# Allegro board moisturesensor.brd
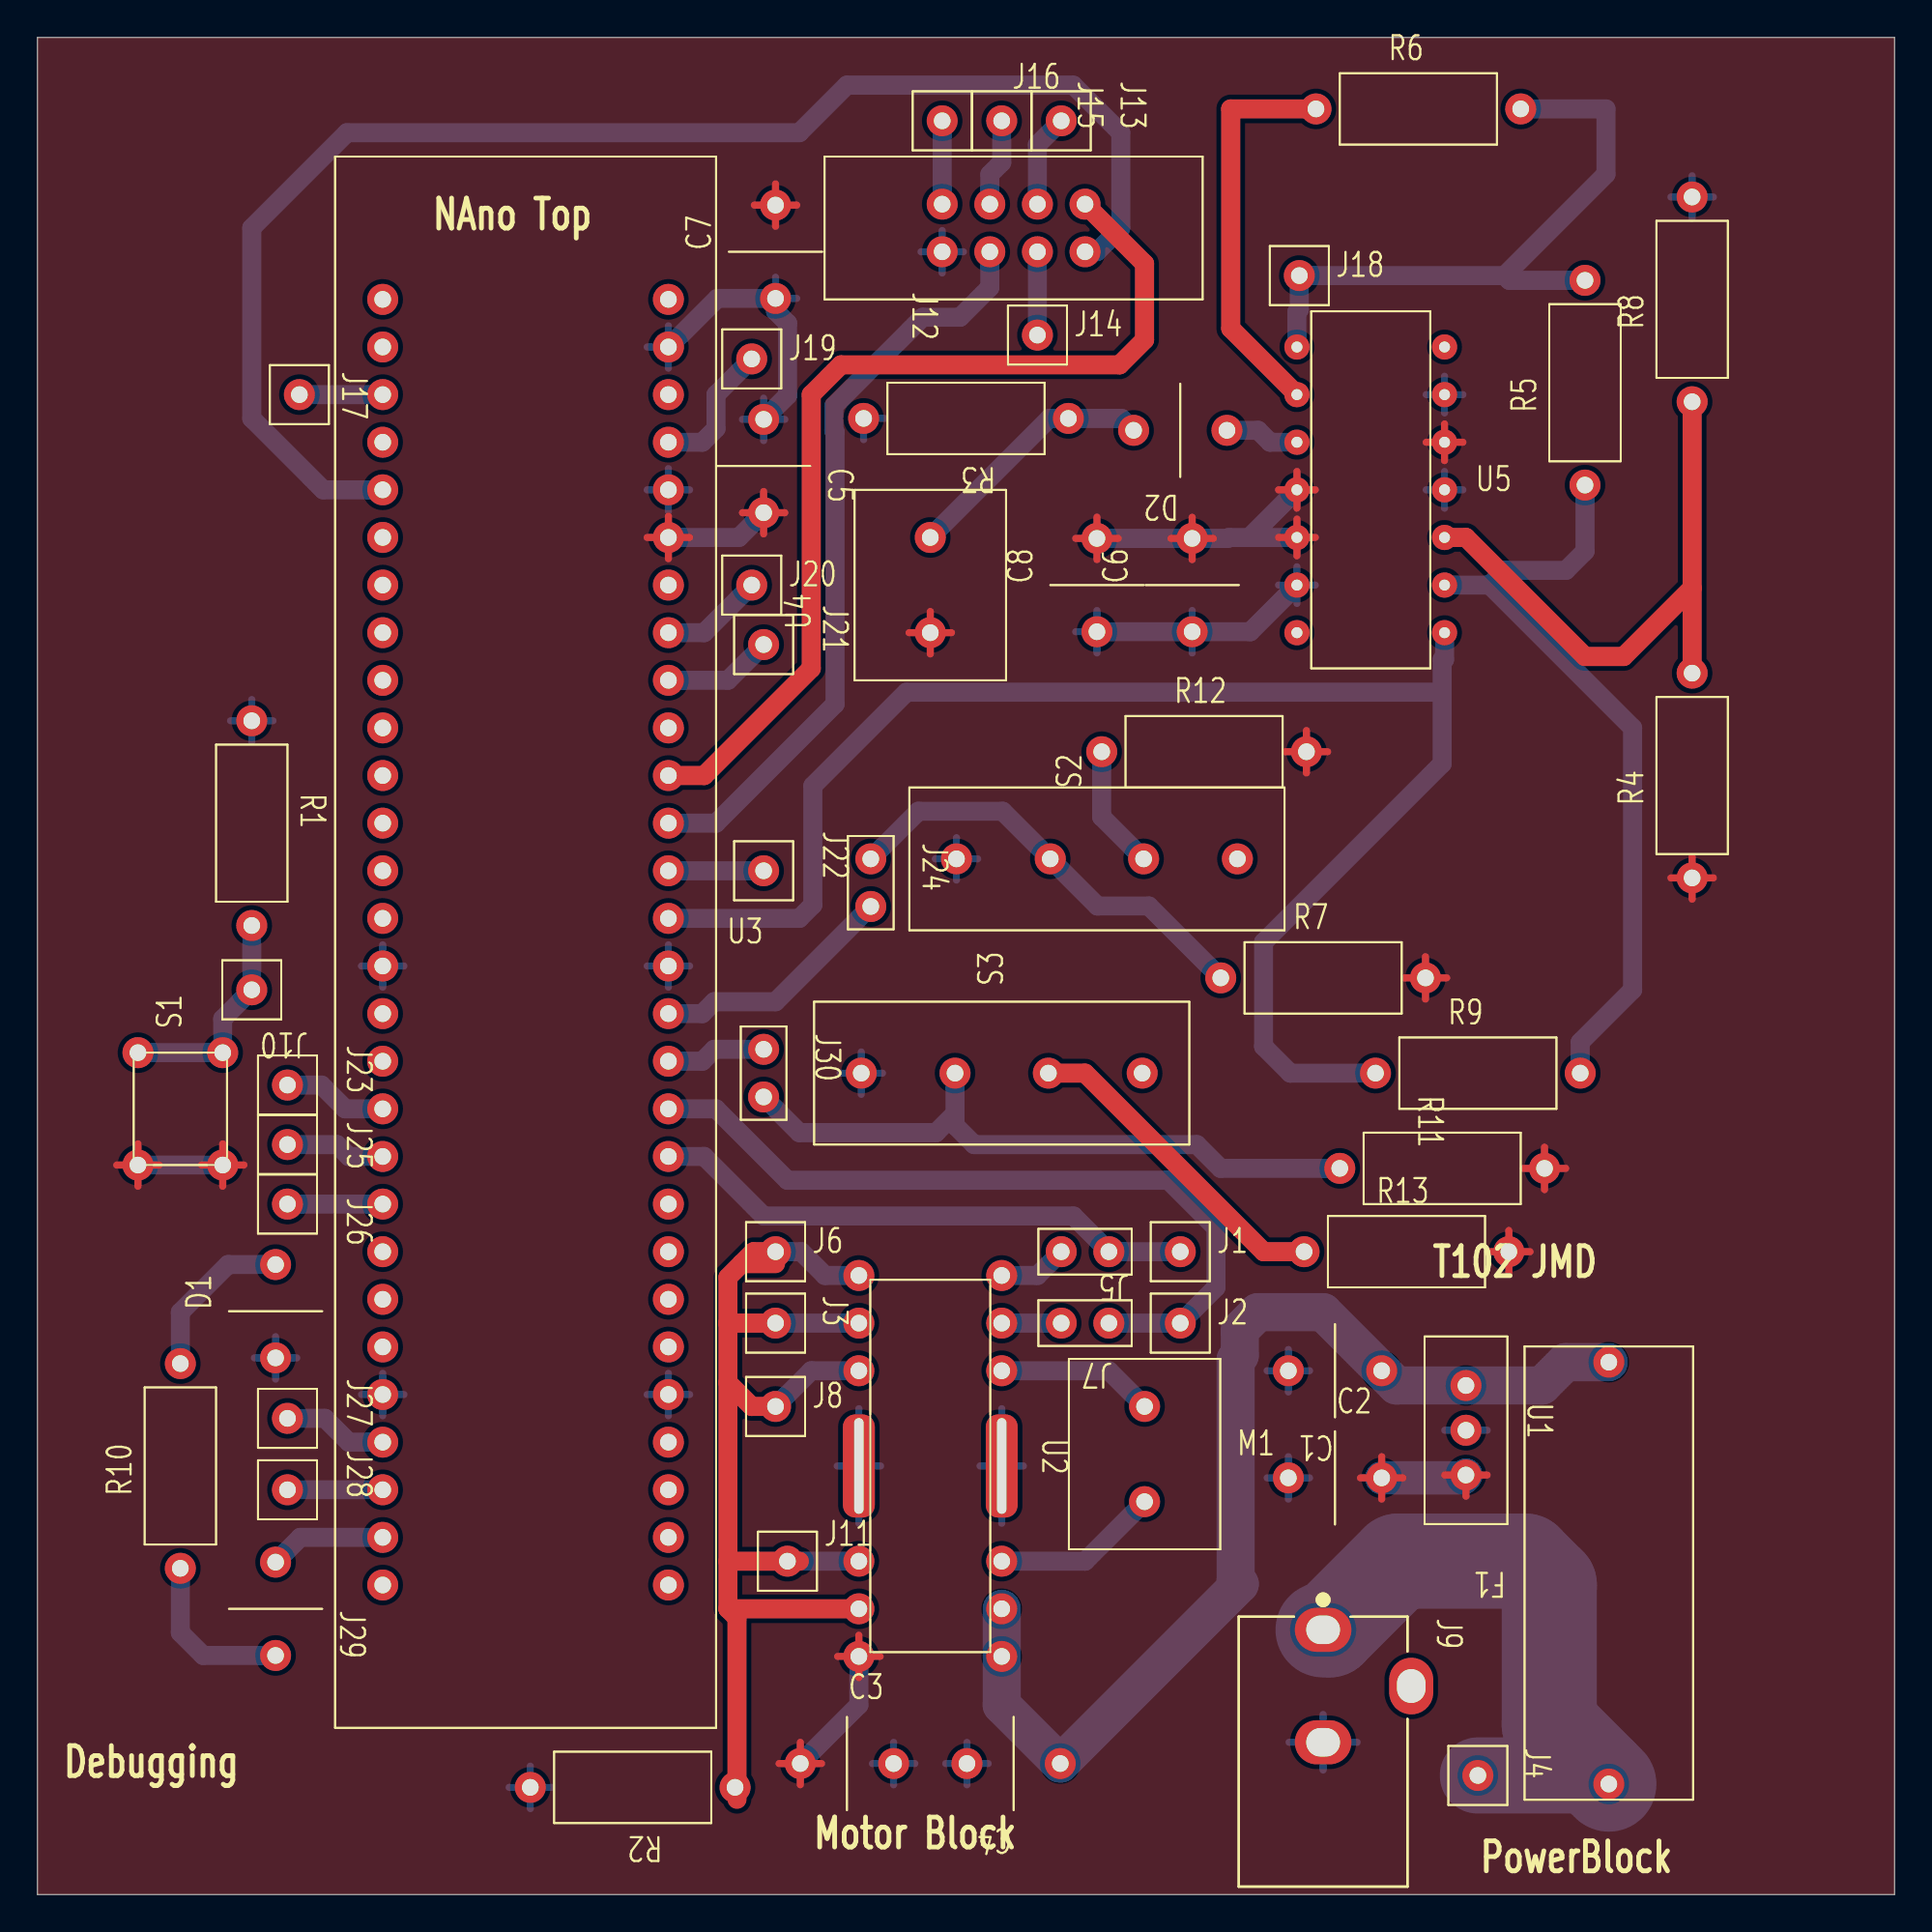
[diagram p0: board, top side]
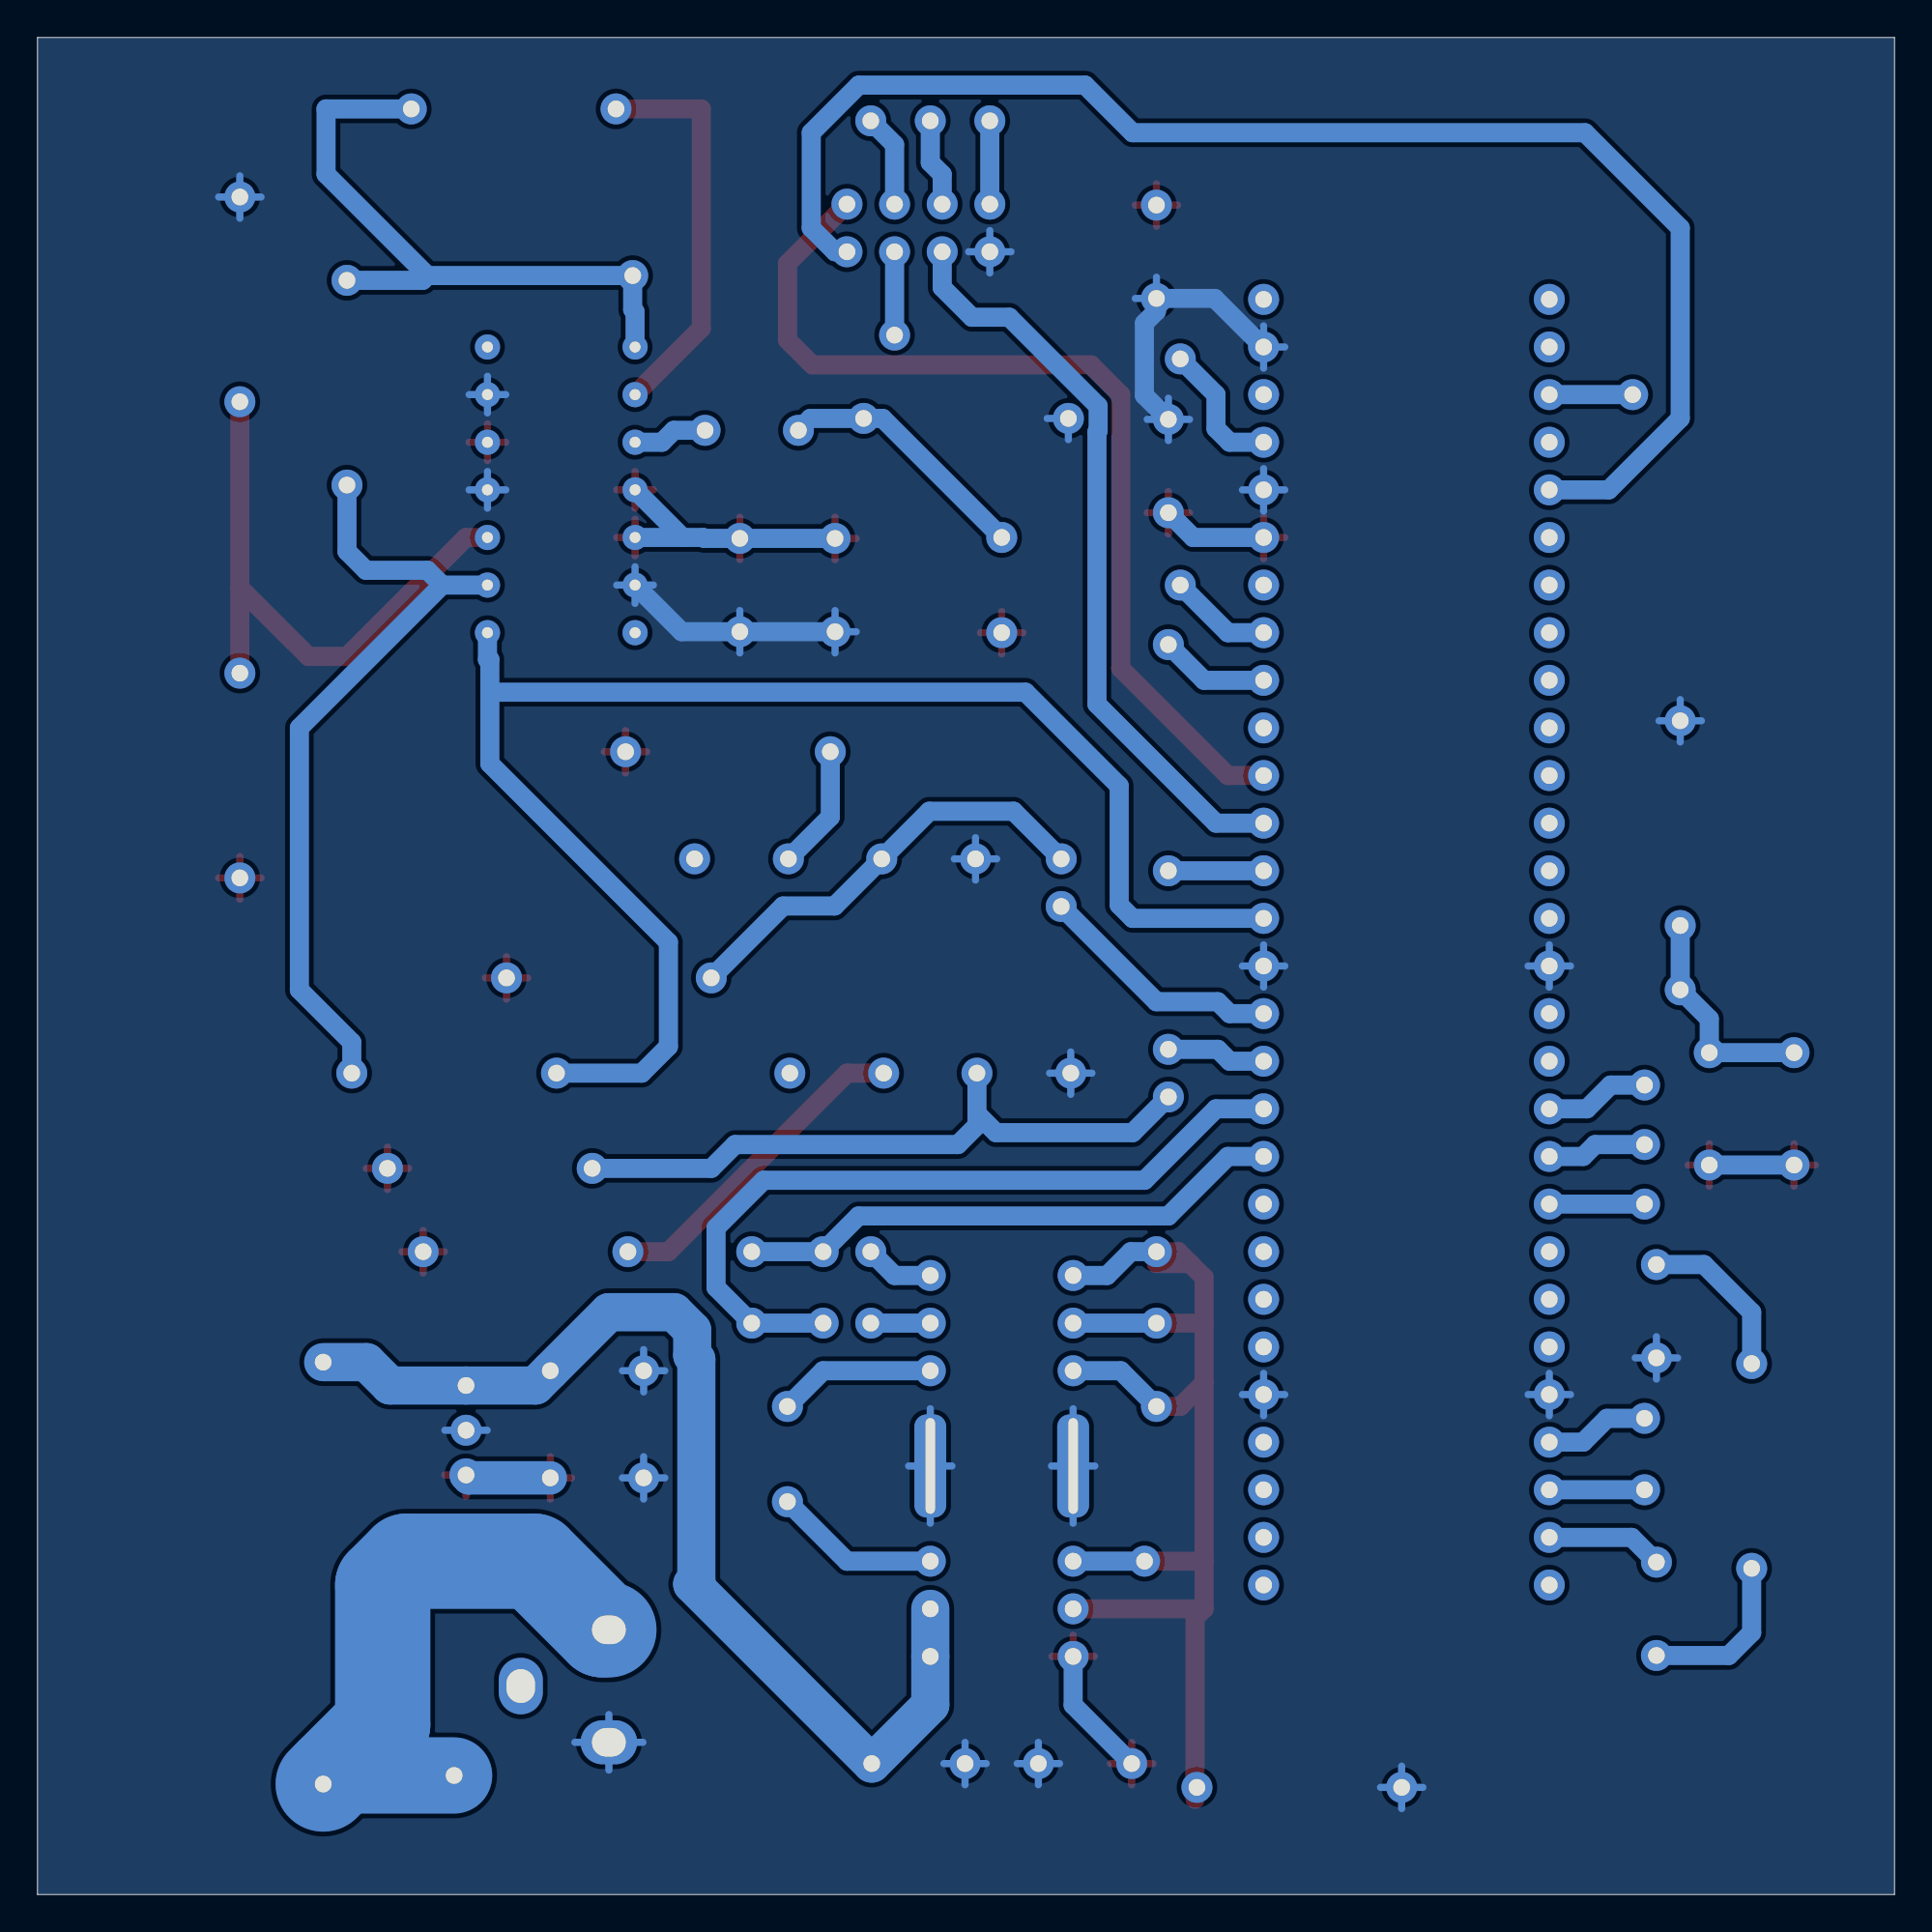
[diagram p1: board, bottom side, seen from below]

Outline 99.06 x 99.06 mm; copper layers: TOP, BOTTOM. Coordinates in mm from the lower left corner of the outline.
Outline path: 0,99.06 0,0 99.06,0 99.06,99.06 0,99.06

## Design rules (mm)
constraint set DEFAULT: min track width 0.381

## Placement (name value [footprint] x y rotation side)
C1  .33uf 50V  [CAPACITOR]  69.22 27.94 180 top
C2  .1uF 50V  [CAPACITOR]  69.22 22.22 0 top
C3  .1uF 50V  [CAPACITOR]  43.18 6.99 0 top
C4  .1uF 50V  [CAPACITOR]  52.07 6.99 180 top
C5  .1uF 50V  [CAPACITOR]  38.73 76.2 270 top
C6  .1uF 50V  [CAPACITOR]  61.59 69.85 90 top
C7  .1uF 50V  [CAPACITOR]  39.37 87.63 90 top
C8  .1uF 50V  [CAPACITOR]  56.52 69.85 90 top
D1  BlueLED  [CAPACITOR]  12.7 31.12 90 top
D2  DIODE  [CAPACITOR]  60.96 78.11 180 top
F1  FUSE 1A  [FUSEHOLDER]  83.82 17.15 180 top
J1  TP2  [MALEPINHOLE]  60.96 34.29 0 top
J2  TP3  [MALEPINHOLE]  60.96 30.48 0 top
J3  TP5  [MALEPINHOLE]  39.37 30.48 0 top
J4  TP12  [MALEPINHOLE]  76.83 6.35 0 top
J5  Jumper_JMD  [JUMPER]  55.88 34.29 270 top
J6  TP4  [MALEPINHOLE]  39.37 34.29 0 top
J7  Jumper_JMD  [JUMPER]  55.88 30.48 270 top
J8  TP6  [MALEPINHOLE]  39.37 26.03 0 top
J9  Barrel_Jack_Switch_JMD  [BARRELJACKDEVELOPERS_JMD]  68.58 7.62 270 top
J10  TP13  [MALEPINHOLE]  11.43 48.26 270 top
J11  TP7  [MALEPINHOLE]  40 17.78 0 top
J12  RibbonCable  [DIP8PIN]  52.07 88.9 270 top
J13  TP8  [MALEPINHOLE]  54.61 94.62 0 top
J14  TP9  [MALEPINHOLE]  53.34 83.19 0 top
J15  TP10  [MALEPINHOLE]  51.44 94.62 0 top
J16  TP11  [MALEPINHOLE]  48.26 94.62 0 top
J17  gpio_RF0  [MALEPINHOLE]  13.97 80.01 0 top
J18  TP1  [MALEPINHOLE]  67.31 86.36 0 top
J19  gpio_RB7  [MALEPINHOLE]  38.1 81.92 0 top
J20  gpio_RA6  [MALEPINHOLE]  38.1 69.85 0 top
J21  gpio_RB3  [MALEPINHOLE]  38.73 66.68 0 top
J22  gpio_RA1  [MALEPINHOLE]  38.73 54.61 0 top
J23  gpio_RE2  [MALEPINHOLE]  13.34 43.18 0 top
J24  Jumper_JMD  [JUMPER]  44.45 53.97 0 top
J25  gpio_RC7  [MALEPINHOLE]  13.34 40 0 top
J26  gpio_RD0  [MALEPINHOLE]  13.34 36.83 0 top
J27  gpio_RF0  [MALEPINHOLE]  13.34 25.4 0 top
J28  gpio_RF1  [MALEPINHOLE]  13.34 21.59 0 top
J29  Jumper_JMD  [CAPACITOR]  12.7 15.24 270 top
J30  Jumper_JMD  [JUMPER]  38.73 43.81 0 top
M1  Motor_DC_JMD  [SCREWTERMINAL]  59.06 23.5 0 top
R1  1k .25w  [RESISTOR_INTRO]  11.43 57.15 270 top
R2  1k .25w  [RESISTOR_INTRO]  31.75 5.72 180 top
R3  10k .25W  [RESISTOR_INTRO]  49.53 78.74 180 top
R4  10k .25W  [RESISTOR_INTRO]  88.27 59.69 90 top
R5  1k .25w  [RESISTOR_INTRO]  82.55 80.64 90 top
R6  1k .25w  [RESISTOR_INTRO]  73.66 95.25 0 top
R7  100k .25W  [RESISTOR_INTRO]  68.58 48.9 0 top
R8  10k .25W  [RESISTOR_INTRO]  88.27 85.09 90 top
R9  10k .25W  [RESISTOR_INTRO]  76.83 43.81 0 top
R10  220 .25W  [RESISTOR_INTRO]  7.62 22.86 90 top
R11  10k .25W  [RESISTOR_INTRO]  74.93 38.74 0 top
R12  10k .25W  [RESISTOR_INTRO]  62.23 60.96 0 top
R13  2k .25W  [RESISTOR_INTRO]  73.03 34.29 0 top
S1  SW_DPST_JMD  [SW_DPST]  7.62 41.91 90 top
S2  Switch_limit_JMD  [LIMITSWITCH]  56.52 55.25 90 top
S3  Switch_limit_JMD  [LIMITSWITCH]  51.44 43.81 90 top
U1  LM7805_JMD  [LINEARVOLTREG]  76.2 24.77 0 top
U2  FAN8011N_JMD  [HBRIDGEWITHFIN]  45.09 22.86 0 top
U3  PIC18F57Q43_JMD  [MICROCHIP_PIC18F57Q43]  26.03 50.8 0 top
U4  MS_JMD  [SCREWTERMINAL]  47.62 69.85 180 top
U5  MCP6004_JMD  [OPAMPJMD]  71.12 74.93 0 top

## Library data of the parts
C1-C8 = CAPACITOR NON-POL
D1 = LED
D2 = DIODE
F1 = FUSE
J1-J4 J6 J10 J13-J17 J20-J23 J25-J28 = MalePinPlaceHolder_JMD
J5 J7 J24 J29 J30 = jumper_jmd
J8 = malePinPlaceHolderOutput_JMD_0
J9 = Barrel_Jack_Switch_JMD
J11 = malePinPlaceHolderOutput_JMD_1
J12 = CONN TRBLK 8
J18 = MalePinPlaceHolder_JMD_6
J19 = malePinPlaceHolderOutput_JMD
M1 = Motor_DC_JMD
R1-R13 = RESISTOR
S1 = SW_DPST_JMD
S2 S3 = 463093691402_Limit_JMD
U1 = LM7805_JMD_0
U2 = FAN8011N_JMD_2
U3 = PIC18F57Q43_JMD
U4 = MoistureSenosr_JMD
U5 = MCP6004_JMD

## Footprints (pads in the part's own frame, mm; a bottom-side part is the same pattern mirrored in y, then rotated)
BARRELJACKDEVELOPERS_JMD
  oval 2.35x3.016 hole 1.52x1.8 unplated: (-6.5,0) (-0.5,0)
  oval 3.016x2.35 hole 1.8x1.52 unplated: (-3.5,4.7)
CAPACITOR
  round 1.651 hole 0.889: 1(-2.489,0) 2(2.489,0)
DIP8PIN
  round 1.651 hole 0.889: 1(-1.27,3.81) 2(1.27,3.81) 3(-1.27,1.27) 4(1.27,1.27) 5(-1.27,-1.27) 6(1.27,-1.27) 7(-1.27,-3.81) 8(1.27,-3.81)
FUSEHOLDER
  round 1.651 hole 0.889: 1(0,11.252) 2(0,-11.252)
HBRIDGEWITHFIN
  round 1.651 hole 0.889: 1(-1.27,10.16) 2(-1.27,7.62) 3(-1.27,5.08) 4(-1.27,-5.08) 5(-1.27,-7.62) 6(-1.27,-10.16) 7(6.35,-10.16) 8(6.35,-7.62) 9(6.35,-5.08) 10(6.35,5.08) 11(6.35,7.62) 12(6.35,10.16)
  rrect 1.7x5.5 hole 0.5x5.105: FIN(-1.27,0) FIN2(6.35,0)
JUMPER
  round 1.651 hole 0.889: 1(0,1.27) 2(0,-1.27)
LIMITSWITCH
  round 1.651 hole 0.889: 1(0,7.493) 2(0,2.489) 3(0,-2.489) 4(0,-7.493)
LINEARVOLTREG
  round 1.651 hole 0.889: 1(0,2.388) 2(0,0) 3(0,-2.388)
MALEPINHOLE
  round 1.651 hole 0.889: 1(0,0)
MICROCHIP_PIC18F57Q43
  round 1.651 hole 0.889: 1(7.62,34.29) 2(7.62,31.75) 3(7.62,29.21) 4(7.62,26.67) 5(7.62,24.13) 6(7.62,21.59) 7(7.62,19.05) 8(7.62,16.51) 9(7.62,13.97) 10(7.62,11.43) 11(7.62,8.89) 12(7.62,6.35) 13(7.62,3.81) 14(7.62,1.27) 15(7.62,-1.27) 16(7.62,-3.81) 17(7.62,-6.35) 18(7.62,-8.89) 19(7.62,-11.43) 20(7.62,-13.97) 21(7.62,-16.51) 22(7.62,-19.05) 23(7.62,-21.59) 24(7.62,-24.13) 25(7.62,-26.67) 26(7.62,-29.21) 27(7.62,-31.75) 28(7.62,-34.29) 29(-7.62,34.29) 30(-7.62,31.75) 31(-7.62,29.21) 32(-7.62,26.67) 33(-7.62,24.13) 34(-7.62,21.59) 35(-7.62,19.05) 36(-7.62,16.51) 37(-7.62,13.97) 38(-7.62,11.43) 39(-7.62,8.89) 40(-7.62,6.35) 41(-7.62,3.81) 42(-7.62,1.27) 43(-7.62,-1.27) 44(-7.62,-3.81) 45(-7.62,-6.35) 46(-7.62,-8.89) 47(-7.62,-11.43) 48(-7.62,-13.97) 49(-7.62,-16.51) 50(-7.62,-19.05) 51(-7.62,-21.59) 52(-7.62,-24.13) 53(-7.62,-26.67) 54(-7.62,-29.21) 55(-7.62,-31.75) 56(-7.62,-34.29)
OPAMPJMD
  round 1.346 hole 0.584: 1(-3.937,7.62) 2(-3.937,5.08) 3(-3.937,2.54) 4(-3.937,0) 5(-3.937,-2.54) 6(-3.937,-5.08) 7(-3.937,-7.62) 8(3.937,-7.62) 9(3.937,-5.08) 10(3.937,-2.54) 11(3.937,0) 12(3.937,2.54) 13(3.937,5.08) 14(3.937,7.62)
RESISTOR_INTRO
  round 1.651 hole 0.889: 1(-5.461,0) 2(5.461,0)
SCREWTERMINAL
  round 1.651 hole 0.889: 1(0,2.54) 2(0,-2.54)
SW_DPST
  round 1.651 hole 0.889: 1(-2.997,2.261) 2(2.997,2.261) 3(-2.997,-2.261) 4(2.997,-2.261)

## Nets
+5V: C2.2 C3.1 C5.2 C6.2 C7.2 C8.2 R4.1 R7.2 R11.2 R12.2 R13.2 S1.1(\PASSIVE\) S1.3 U1.3(\OUTPUT\) U2.6(\VCC\) U3.6(\VTG\) U4.1 U5.4 U5.5 U5.12
+9V: C1.1 C4.1 F1.2 U1.1 U2.7 U2.8
GND: C1.2 C2.1 C3.2 C4.2 C5.1 C6.1 C7.1 C8.1 D1.1(\CATHODE\) J12.8 R1.1 R2.2 R3.2 R8.2 S2.1 S3.1 U1.2 U2.FIN U2.FIN2 U3.2 U3.5 U3.15 U3.24 U3.43 U3.52 U5.6 U5.11(\VSS\) U5.13
VBUS: U3.1
AMPSIG: R5.1 R9.2 U5.9
BACKLIMIT: J30.1 U3.17
INVAMP: R6.1 U5.2
MRETURN: J12.6 U3.12
MSOUT: R9.1 U3.14 U5.8
OUT1: J18.1(\PORT\) R5.2 R6.2 U5.1
PSIGNAL: J12.1 U3.11
RSIGNAL: J12.2 U3.33
SIGBACK: J1.1(\PORT\) J5.1 U3.19
SIGFORWARD: J2.1(\PORT\) J7.1 U3.18
VREF: R4.2 R8.1 U5.10
N91840: J3.1(\PORT\) J6.1(\PORT\) J8.1 J11.1 R2.1 U2.1 U2.2 U2.3 U2.4 U2.5
N91848: J7.2 U2.11
N91894: M1.1 U2.10
N91902: F1.1 J4.1(\PORT\)
N92202: M1.2(-) U2.9
N93412: J24.2 U3.16
N93642: J27.1(\PORT\) U3.53
N93710: J29.1 U3.55
N93718: J29.2 R10.1
N93780: J30.2 R11.1 S3.2
N93800: R13.1 S3.3
N113659: J10.1(\PORT\) R1.2 S1.2 S1.4
N116351: J24.1 R7.1 S2.2
N125765: D2.2 R3.1 U4.2
N125778: D2.1(\K\) U5.3
N129031: J12.4 J14.1(\PORT\)
N923142: J12.3 J13.1(\PORT\)
N923144: J12.5 J15.1(\PORT\)
N923146: J12.7 J16.1(\PORT\)
N926043: J19.1 U3.4
N926047: J20.1(\PORT\) U3.8
N926048: J21.1(\PORT\) U3.9
N932342: R12.1 S2.3
N934900: D1.2 R10.2
N9170211: J5.2 U2.12
N9260427: J17.1(\PORT\) U3.31
N9260442: J23.1(\PORT\) U3.46
N9260443: J25.1(\PORT\) U3.47
N9260444: J26.1(\PORT\) U3.48
N9260450: J28.1(\PORT\) U3.54
N9260454: J22.1(\PORT\) U3.13

Pads without a net: S2 4; S3 4; U3 3 7 10 20 21 22 23 25 26 27 28 29 30 32 34 35 36 37 38 39 40 41 42 44 45 49 50 51 56; U5 7 14

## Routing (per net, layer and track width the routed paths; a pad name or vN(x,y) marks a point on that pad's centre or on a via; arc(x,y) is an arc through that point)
+5V: length 123.5
  TOP w0.381: 46.49,67.31 U4.1 ; U4.1 47.62,68.44 ; U4.1 47.62,66.18 ; U4.1 48.76,67.31 ; 87.13,54.23 R4.1 ; R4.1 88.27,53.1 ; R4.1 88.27,55.36 ; R4.1 89.4,54.23 ; 55.38,72.34 C8.2 ; C8.2 56.52,71.21 ; C8.2 57.65,72.34 ; C8.2 56.52,73.47 ; 37.6,73.71 C5.2 ; C5.2 39.87,73.71 ; C5.2 38.73,74.84 ; C5.2 38.73,72.58 ; 71.7,21.09 C2.2 ; C2.2 72.84,22.22 ; C2.2 71.7,23.36 ; C2.2 70.57,22.22 ; 5.36,37.78 S1.1 ; S1.1 6.49,38.91 ; S1.1 5.36,40.04 ; S1.1 4.23,38.91 ; R7.2 74.04,50.03 ; R7.2 72.91,48.9 ; R7.2 74.04,47.76 ; R7.2 75.17,48.9 ; C7.2 40.5,90.12 ; C7.2 39.37,88.99 ; C7.2 39.37,91.25 ; C7.2 38.24,90.12 ; R13.2 78.49,35.42 ; R13.2 77.36,34.29 ; R13.2 78.49,33.16 ; R13.2 79.62,34.29 ; R11.2 81.52,38.74 ; R11.2 79.26,38.74 ; R11.2 80.39,37.6 ; R11.2 80.39,39.87 ; U5.12 75.06,78.45 ; U5.12 75.06,76.49 ; U5.12 76.04,77.47 ; U5.12 74.08,77.47 ; U5.5 68.16,72.39 ; U5.5 67.18,71.41 ; U5.5 67.18,73.37 ; U5.5 66.2,72.39 ; 42.68,12.7 U2.6 ; U2.6 44.95,12.7 ; U2.6 43.81,13.83 ; U2.6 43.81,11.57 ; S1.3 9.88,40.04 ; S1.3 11.01,38.91 ; S1.3 9.88,37.78 ; S1.3 8.75,38.91 ; 76.2,21.25 U1.3 ; U1.3 75.07,22.38 ; U1.3 77.33,22.38 ; C6.2 62.73,72.34 ; C6.2 61.59,73.47 ; C6.2 61.59,71.21 ; C6.2 60.46,72.34 ; U5.4 67.18,75.91 ; U5.4 68.16,74.93 ; U5.4 66.2,74.93 ; U5.4 67.18,73.95 ; U3.6 33.66,73.52 ; U3.6 32.52,72.39 ; U3.6 33.66,71.26 ; U3.6 34.79,72.39 ; C3.1 41.82,6.99 ; C3.1 40.69,5.85 ; C3.1 40.69,8.12 ; C3.1 39.56,6.99 ; 67.69,59.83 R12.2 ; R12.2 67.69,62.09 ; R12.2 66.56,60.96 ; R12.2 68.82,60.96
  BOTTOM w1.016: U3.6 37.41,72.39 C5.2 ; 64.64,72.39 63.55,72.39 63.5,72.34 C6.2 C8.2 ; 64.64,72.39 U5.5 ; 64.64,72.39 U5.4 ; C3.1 43.81,10.11 U2.6 ; S1.1 S1.3
  BOTTOM w1.778: C2.2 76.05,22.22 U1.3
+9V: length 59
  BOTTOM w2.032: U2.8 U2.7 51.44,10.11 C4.1 64.14,16.56 63.91,16.78 63.91,28.55 64.14,28.77 64.14,30.1 65.1,31.06 68.58,31.06 C1.1 72.49,27.15 U1.1 80.26,27.15 81.5,28.4 F1.2
GND: length 153.6
  BOTTOM w0.381: U3.24 33.66,27.8 ; U3.24 33.66,25.54 ; U3.24 32.52,26.67 ; U3.24 34.79,26.67 ; 74.08,80.01 U5.13 ; U5.13 76.04,80.01 ; U5.13 75.06,79.03 ; U5.13 75.06,80.99 ; U5.6 67.18,70.83 ; U5.6 66.2,69.85 ; U5.6 67.18,68.87 ; U5.6 68.16,69.85 ; R8.2 89.4,90.55 ; R8.2 87.13,90.55 ; R8.2 88.27,91.68 ; R8.2 88.27,89.42 ; 68.58,8.12 70.39,8.12 ; 68.58,8.12 68.58,6.64 ; 68.58,8.12 66.77,8.12 ; 68.58,8.12 68.58,9.6 ; U5.11 75.06,75.91 ; U5.11 74.08,74.93 ; U5.11 75.06,73.95 ; U5.11 76.04,74.93 ; C2.1 66.73,23.36 ; C2.1 66.73,21.09 ; C2.1 65.59,22.22 ; C2.1 67.86,22.22 ; 65.59,27.94 C1.2 ; C1.2 67.86,27.94 ; C1.2 66.73,26.81 ; C1.2 66.73,29.07 ; 37.6,78.69 C5.1 ; C5.1 38.73,77.56 ; C5.1 39.87,78.69 ; C5.1 38.73,79.82 ; 45.2,78.74 R3.2 44.07,77.61 ; U3.43 19.55,49.53 ; U3.43 17.28,49.53 ; U3.43 18.42,50.66 ; U3.43 18.42,48.4 ; 49.02,54.11 S2.1 ; S2.1 47.89,55.25 ; S2.1 50.15,55.25 ; S2.1 49.02,56.38 ; S3.1 45.07,43.81 ; S3.1 43.94,44.95 ; S3.1 43.94,42.68 ; S3.1 42.81,43.81 ; 50.28,22.86 U2.FIN2 ; U2.FIN2 51.44,19.8 ; U2.FIN2 51.44,25.92 ; U2.FIN2 52.59,22.86 ; C4.2 50.71,6.99 ; C4.2 49.58,5.85 ; C4.2 49.58,8.12 ; C4.2 48.45,6.99 ; U3.15 34.79,49.53 ; U3.15 32.52,49.53 ; U3.15 33.66,48.4 ; U3.15 33.66,50.66 ; 11.43,61.48 R1.1 ; R1.1 11.43,63.74 ; R1.1 10.3,62.61 ; R1.1 12.56,62.61 ; 39.37,86.27 C7.1 40.5,85.14 ; U3.52 18.42,27.8 ; U3.52 17.28,26.67 ; U3.52 19.55,26.67 ; U3.52 18.42,25.54 ; J12.8 48.26,88.76 ; J12.8 48.26,86.5 ; J12.8 49.39,87.63 ; J12.8 47.13,87.63 ; 32.52,74.93 U3.5 ; U3.5 33.66,76.06 ; U3.5 34.79,74.93 ; U3.5 33.66,73.8 ; C3.2 46.8,6.99 ; C3.2 45.67,8.12 ; C3.2 45.67,5.85 ; C3.2 44.54,6.99 ; 56.52,66.23 C8.1 ; C8.1 56.52,68.49 ; C8.1 55.38,67.36 ; U3.2 33.66,83.68 ; U3.2 33.66,81.42 ; U3.2 32.52,82.55 ; 61.59,66.23 C6.1 61.59,68.49 ; U2.FIN 44.97,22.86 ; U2.FIN 42.66,22.86 ; U2.FIN 43.81,25.92 ; U2.FIN 43.81,19.8 ; 77.33,24.77 U1.2 75.07,24.77 ; D1.1 13.83,28.63 ; D1.1 12.7,29.76 ; D1.1 12.7,27.49 ; D1.1 11.57,28.63 ; 25.16,5.72 R2.2 ; R2.2 27.42,5.72 ; R2.2 26.29,6.85 ; R2.2 26.29,4.58
  BOTTOM w1.016: U5.6 64.69,67.36 C6.1 C8.1 ; C5.1 40.01,79.97 40.01,83.82 39.37,84.46 C7.1 36.26,85.14 33.67,82.55 U3.2
AMPSIG: length 42.1
  BOTTOM w1.016: 77.47,69.85 85.09,62.23 85.09,48.26 82.3,45.47 R9.2 ; 77.47,69.85 U5.9 ; 77.47,69.85 78.26,70.64 81.53,70.64 82.55,71.65 R5.1
BACKLIMIT: length 5.3
  BOTTOM w1.016: J30.1 36.1,45.09 35.46,44.45 U3.17
INVAMP: length 21.2
  TOP w1.016: U5.2 63.65,83.54 63.65,95.25 R6.1
MRETURN: length 40.3
  BOTTOM w1.016: 50.8,87.63 50.8,85.73 49.21,84.14 47.22,84.14 42.48,79.4 42.48,78.08 42.55,78.02 42.55,63.5 36.2,57.15 U3.12
MSOUT: length 82.7
  BOTTOM w1.016: 74.93,64.13 74.93,65.88 75.06,65.88 U5.8 ; 74.93,64.13 46.36,64.13 41.36,59.14 41.36,52.79 40.64,52.07 U3.14 ; 74.93,64.13 74.93,60.33 65.41,50.8 65.41,45.24 66.83,43.81 R9.1
OUT1: length 34.9
  BOTTOM w1.016: 78.26,86.36 83.67,91.77 83.67,95.25 R6.2 ; 78.26,86.36 J18.1 67.31,84.55 67.18,84.43 U5.1 ; 78.26,86.36 78.51,86.11 R5.2
PSIGNAL: length 52.1
  TOP w1.016: 55.88,90.17 59.06,87 59.06,82.93 57.72,81.6 42.86,81.6 41.28,80.01 41.28,65.41 35.56,59.69 U3.11
RSIGNAL: length 76.8
  BOTTOM w1.016: U3.33 15.24,74.93 11.43,78.74 11.43,88.9 16.51,93.98 40.64,93.98 43.18,96.52 55.25,96.52 57.78,93.98 57.78,88.9 56.52,87.63 55.88,87.63
SIGBACK: length 29.4
  BOTTOM w1.016: J1.1 57.15,34.29 57.15,34.31 55.26,36.19 38.73,36.19 35.56,39.37 U3.19
SIGFORWARD: length 41.5
  BOTTOM w1.016: U3.18 36.2,41.91 40,38.1 60.33,38.1 62.86,35.56 62.86,32.38 J2.1 57.15,30.48
VREF: length 31.8
  TOP w1.016: R4.2 88.27,69.7 ; 88.27,69.7 84.61,66.04 82.55,66.04 76.2,72.39 U5.10 ; 88.27,69.7 R8.1
N91840: length 67.8
  TOP w1.016: 36.83,15.24 36.83,17.78 ; 36.83,15.24 U2.5 ; 36.83,15.24 37.31,14.76 37.31,5.08 ; 36.83,17.78 J11.1 40.64,17.78 ; 36.83,17.78 36.83,27.31 ; J3.1 36.83,30.48 ; 36.83,30.48 36.83,32.92 37.57,33.66 ; 36.83,30.48 36.83,27.31 ; 37.57,33.66 38.2,34.29 J6.1 ; 37.57,33.66 39.37,33.66 ; 36.83,27.31 38.1,26.03 J8.1
  BOTTOM w1.016: J11.1 U2.4 ; U2.2 J3.1 ; J6.1 40.74,34.29 42.01,33.02 U2.1 ; U2.3 41.28,27.94 J8.1
N91848: length 3.2
  BOTTOM w1.016: J7.2 U2.11
N91894: length 8.4
  BOTTOM w1.016: U2.10 57.15,27.94 M1.1
N91902: length 32.6
  BOTTOM w4.064: 83.36,6.35 J4.1
  BOTTOM w5.08: F1.1 80.64,9.07 80.64,16.51 79.38,17.78 72.57,17.78 68.91,14.12 68.58,14.12
N92202: length 8.9
  BOTTOM w1.016: M1.2 55.88,17.78 U2.9
N93412: length 13.2
  BOTTOM w1.016: J24.2 39.37,47.62 36.1,47.62 35.46,46.99 U3.16
N93642: length 5.6
  BOTTOM w1.016: U3.53 16.61,24.13 15.34,25.4 J27.1
N93710: length 6.3
  BOTTOM w1.016: J29.1 14.02,19.05 U3.55
N93718: length 9
  BOTTOM w1.016: J29.2 8.84,12.75 7.62,13.97 R10.1
N93780: length 35.7
  BOTTOM w1.016: R11.1 63.11,38.74 61.84,40 49.96,40 48.95,41.02 48.95,41.66 ; 48.95,41.66 47.93,40.64 40.64,40.64 J30.2 ; 48.95,41.66 S3.2
N93800: length 17.6
  TOP w1.016: R13.1 65.41,34.29 55.88,43.81 S3.3
N113659: length 11.9
  BOTTOM w1.016: S1.2 S1.4 9.88,46.71 J10.1 R1.2
N116351: length 23.4
  BOTTOM w1.016: R7.1 59.28,52.73 56.54,52.73 S2.2 51.49,57.78 46.99,57.78 J24.1
N125765: length 13.7
  BOTTOM w1.016: D2.2 57.84,78.74 R3.1 53.98,78.74 U4.2
N125778: length 4
  BOTTOM w1.016: D2.1 65.11,78.11 65.75,77.47 U5.3
N129031: length 4.4
  BOTTOM w1.016: J14.1 J12.4
N923142: length 5
  BOTTOM w1.016: J12.3 53.34,93.35 J13.1
N923144: length 4.7
  BOTTOM w1.016: 50.8,90.17 50.8,91.76 51.44,92.39 J15.1
N923146: length 4.4
  BOTTOM w1.016: J16.1 J12.7
N926043: length 7.3
  BOTTOM w1.016: U3.4 35.46,77.47 36.2,78.2 36.2,80.01 J19.1
N926047: length 5.5
  BOTTOM w1.016: J20.1 35.56,67.31 U3.8
N926048: length 5.9
  BOTTOM w1.016: U3.9 36.83,64.77 J21.1
N932342: length 6.6
  BOTTOM w1.016: S2.3 56.77,57.48 R12.1
N934900: length 8.9
  BOTTOM w1.016: D1.2 10.16,33.6 7.62,31.06 7.62,28.32
N9170211: length 3.7
  BOTTOM w1.016: J5.2 53.34,33.02 U2.12
N9260427: length 4.4
  BOTTOM w1.016: J17.1 U3.31
N9260442: length 5.6
  BOTTOM w1.016: J23.1 15.14,43.18 16.41,41.91 U3.46
N9260443: length 5.3
  BOTTOM w1.016: U3.47 16.61,39.37 15.97,40 J25.1
N9260444: length 5.1
  BOTTOM w1.016: U3.48 J26.1
N9260450: length 5.1
  BOTTOM w1.016: U3.54 J28.1
N9260454: length 5.1
  BOTTOM w1.016: U3.13 J22.1

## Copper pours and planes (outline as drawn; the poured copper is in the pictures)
+5V on TOP: 0,99.06 0,0 99.06,0 99.06,99.06
GND on BOTTOM: 99.06,0 99.06,99.06 0,99.06 0,0

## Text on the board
Ref Des/Silkscreen Top: Debugging | NAno Top | Motor Block | T102 JMD | PowerBlock
NCROUTE_PATH: Dirks | 102
